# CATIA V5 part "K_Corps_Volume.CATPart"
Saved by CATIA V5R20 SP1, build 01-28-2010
Part number: corps_volume
Publications: "Plan.6", "Raccord roue avant", "Droite.23", "diamètre des barres", "Surepaisseur du tube", "diamètre doight pivot roue avant", "épaisseur raccord", "barres pour roues principales", "raccord des barres principales", "barres soutien", "raccord barres soutien", "petite barre soutien"
Bounding box of the stored display mesh (mm): x -80 to 825, y -400 to 400, z -136.807 to 80
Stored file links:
  G:\Khaled_CFAO_2011\ST2M\ST2M_GR1\cdurantin\cdurantin\Khaled\CAD_ThinkMOTION\K_Corps_Volume.CATPart
  G:\Khaled_CFAO_2011\ST2M\ST2M_GR1\cdurantin\cdurantin\Khaled\CAD_ThinkMOTION\K_Corps.CATPart
  C:\Documents and Settings\cdurantin\Bureau\cdurantin\caddy.CATProduct
  G:\Khaled_CFAO_2011\ST2M\ST2M_GR1\cdurantin\cdurantin\CATIA\Part2.CATPart
  G:\Khaled_CFAO_2011\ST2M\ST2M_GR1\cdurantin\cdurantin\CATIA\pivot roue avant.CATPart
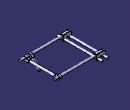
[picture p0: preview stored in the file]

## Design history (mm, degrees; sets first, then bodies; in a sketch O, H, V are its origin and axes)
Parameters
  `diamètre des barres` = 40 mm
  `épaisseur raccord` = 50 mm {= `diamètre des barres` +`Surepaisseur du tube`}
  `Surepaisseur du tube` = 10 mm
  `diamètre doight pivot roue avant` = 5 mm
External parameters (linked from other documents)
  `External.Longueur de barres du corps` = 800 mm
  `External.ecart entre barres de soutien` = 600 mm
  `External.Ecart entre les barres du corps` = 100 mm
  `External.longueur des barres de soutien` = 800 mm
  `External.niveau de la roue avant` = 850 mm
  `External.diamètre tube pivot` = 20 mm
Set1
  Line1 to Line5: linked copy from another document
  Point1: linked copy from another document
  Point2: linked copy from another document
Body1 "barres pour roues principales" (main body)
  Line6: stored without definition
  Point3: stored without definition
  Line7 to Line9: stored without definition
  Sketch1 on zx-plane, origin (0, 0, 0), H (-1, 0, 0), V (0, 0, 1)
    point P1 (-50, 0)
    circle A1 centre (-50, 0) radius 20
    reference projected point E1 (-50, 0) from Line1
    radius A1 = 20 {= `diamètre des barres` /2}
    coincidence: E1 P1
  Pad1: profile Sketch1, direction (0, 1, 0), length 400 {= `External.Longueur de barres du corps` /2}, mirrored extent
  Mirror1: of the body so far, about yz-plane
  Plane1: type Offset, RefPlane zx-plane, Offset 300 {= `External.ecart entre barres de soutien` /2}
  Point4: stored without definition
  Line10: stored without definition
  DatumPoint1
  Line11: stored without definition
  DatumPoint2
  DatumPoint3
  Point5: stored without definition
Body2 "raccord des barres principales"
  Line12: stored without definition
  Line13: stored without definition
  Sketch2 on Plane1, origin (0, 300, 0), H (-1, 0, 0), V (0, 0, 1)
    arc A1 centre (-50, 0) radius 30 from (-80, 0) to (-20, 0) ccw
    arc A2 centre (0, 0) radius 20 from (0, 20) to (-20, 0) ccw
    point P2 (0, 0)
    point P3 (50, 0)
    point P4 (-20, 0)
    reference projected line E1 (100, 0) -> (0, 0) from Line10
    line L1 (-20, 0) -> (-20, 0)
    point P5 (-20, 0)
    point P6 (0, 20)
    line L2 (0, 20) -> (0, 80)
    line L3 (0, 80) -> (-80, 80)
    line L4 (-80, 80) -> (-80, 0)
    point P9 (-80, 0)
    point P10 (-80, 0)
    point P11 (-20, 0)
    reference projected point E2 (0, 0) from Point5
    circle A3 centre (-50, 0) radius 20
    point P12 (-50, 0)
    reference projected point E3 (-50, 0) from axis of face of Pad1 from Sketch1.A1
    radius A1 = 30 {= `Surepaisseur du tube` +`diamètre des barres` /2}
    distance A2 E1 = 20 {= `diamètre des barres` /2}
    length L2 = 60 {= 2*`Surepaisseur du tube` +`diamètre des barres`}
    length L3 = 80 {= `Surepaisseur du tube` +`diamètre des barres` /2+`External.Ecart entre les barres du corps` /2}
    distance P4 E2 = 20 {= `External.Ecart entre les barres du corps` /2-(`diamètre des barres` /2+`Surepaisseur du tube` )}
    radius A3 = 20 {= `diamètre des barres` /2}
    coincidence: P2 V, P3 H, P4 H, P5 A1, P6 V, P9 A1, L1 P11, L4 P10, P5 P11, P9 P10, E3 P12
    horizontal: L1 H, L3 H
    vertical: L2 V
    tangency: L4 A1
    concentricity: A1 A3
  Pad2: profile Sketch2, direction (0, 1, 0), length 25 {= `épaisseur raccord` /2}, mirrored extent
  Mirror2: of the body so far, about yz-plane
  Sketch3 on face of Pad2 from Sketch2.L4, origin (80, 150.6678, 36.0915), H (0, 1, 0), V (0, 0, 1)
    point P1 (149.3322, 13.9085)
    reference projected line E1 (174.3322, 13.9085) -> (174.3322, -36.0915) from edge [face of Pad2 from Sketch2.L4 | end face of Pad2]
    reference projected line E2 (-13.1678, 43.9085) -> (11.8322, 43.9085) from edge [face of Pad2 from Sketch2.L4 | face of Pad2 from Sketch2.L3]
    distance P1 E1 = 25 {= `épaisseur raccord` /2}
    distance P1 E2 = 30 {= `Surepaisseur du tube` +`diamètre des barres` /2}
  Hole1: placed by Sketch3, at (80, 300, 50) direction (-1, 0, 0), diameter 40 {= `diamètre des barres`}, depth 130 {= `Surepaisseur du tube` +`External.Ecart entre les barres du corps` +`diamètre des barres` /2}
  Fillet1: radius 40 {= `diamètre des barres`}, on edge [face of Pad2 | face of Mirror2]
  Fillet2: radius 5, on edge [face of Pad2 | face of Pad2] (x2); edge [face of Pad2 from Sketch2.L4 | face of Pad2]
  Mirror3: of the body so far, about zx-plane
Body3 "barres soutien"
  Plane2 "plan de construction": type Offset, RefPlane yz-plane, Offset 425 {= `External.niveau de la roue avant` /2}
  Sketch4 on Plane2, origin (425, 0, 0), H (0, 1, 0), V (0, 0, 1)
    circle A1 centre (-300, 50) radius 20
    point P1 (-300, 50)
    reference projected point E1 (-300, 50) from Line2
    radius A1 = 20 {= `diamètre des barres` /2}
    coincidence: P1 E1
  Pad3: profile Sketch4, direction (1, 0, 0), length 400 {= `External.longueur des barres de soutien` /2}, mirrored extent
  Plane3: type Offset, RefPlane yz-plane, Offset 400 {= `External.longueur des barres de soutien` /2}
  Sketch5 on Plane3, origin (400, 0, 0), H (0, 1, 0), V (0, 0, 1)
    reference projected point E1 (300, 50) from Line3
    circle A1 centre (300, 50) radius 20
    point P1 (300, 50)
    radius A1 = 20 {= `diamètre des barres` /2}
    coincidence: E1 P1
  Pad4: profile Sketch5, direction (1, 0, 0), length 400 {= `External.longueur des barres de soutien` /2}, mirrored extent
Body4 "raccord barres soutien"
  Plane4: type Offset, RefPlane yz-plane, Offset 720 {= `External.longueur des barres de soutien` -`External.longueur des barres de soutien` /10}
  Sketch6 on Plane4, origin (720, 0, 0), H (0, 1, 0), V (0, 0, 1)
    reference projected point E1 (-300, 50) from Line2
    circle A1 centre (-300, 50) radius 20
    arc A2 centre (-300, 50) radius 25 from (-275, 50) to (-325, 50) ccw
    line L1 (-325, 50) -> (-325, 0)
    line L2 (-325, 0) -> (-225, 0)
    line L3 (-225, 0) -> (-225, 50)
    line L4 (-225, 50) -> (-275, 50)
    radius A1 = 20 {= `diamètre des barres` /2}
    radius A2 = 25 {= `diamètre des barres` /2+`Surepaisseur du tube` /2}
    length L2 = 100 {= `épaisseur raccord` *2}
    length L4 = 50 {= `épaisseur raccord`}
    length L3 = 50 {= `épaisseur raccord`}
    distance L2 H = 0
    concentricity: A1 E1, A2 A1
    tangency: L1 A2
    horizontal: L2 H, L4 H
    vertical: L3 V
  Pad5: profile Sketch6, direction (1, 0, 0), length 25 {= `épaisseur raccord` /2}, mirrored extent
  Fillet3: radius 40 {= `diamètre des barres`}, on edge [face of Pad5 from Sketch6.L2 | face of Pad5 from Sketch6.L1]
  Sketch7 on face of Pad5 from Sketch6.L3, origin (719.5732, -225, 15.4267), H (1, 0, 0), V (0, 0, -1)
    point P1 (0.4268, -9.5733)
    reference projected line E1 (-14.5732, 15.4267) -> (15.4268, 15.4267) from edge [face of Pad5 from Sketch6.L3 | face of Pad5 from Sketch6.L2]
    reference projected line E2 (-24.5732, 15.4267) -> (-24.5732, -14.5733) from edge [start face of Pad5 | face of Pad5 from Sketch6.L3]
    distance P1 E1 = 25 {= `épaisseur raccord` /2}
    distance P1 E2 = 25 {= `épaisseur raccord` /2}
  Hole2: placed by Sketch7, at (720, -225, 25) direction (0, -1, 0), diameter 40 {= `diamètre des barres`}, depth 50 {= `épaisseur raccord`}
  Fillet4: radius 5, on edge [face of Pad5 from Sketch6.A2 | face of Pad5 from Sketch6.L4]; edge [face of Pad5 from Sketch6.L4 | end face of Pad5]; edge [start face of Pad5 | face of Pad5 from Sketch6.L4]; edge [face of Pad5 from Sketch6.L4 | face of Pad5 from Sketch6.L3]; edge [face of Pad5 from Sketch6.L3 | end face of Pad5]; edge [start face of Pad5 | face of Pad5 from Sketch6.L3]; edge [face of Pad5 from Sketch6.L3 | face of Pad5 from Sketch6.L2]; edge [face of Pad5 from Sketch6.L2 | end face of Pad5]; edge [start face of Pad5 | face of Pad5 from Sketch6.L2]
  Mirror4: of the body so far, about zx-plane
Body5 "petite barre soutien"
  Sketch8 on Plane4, origin (720, 0, 0), H (0, 1, 0), V (0, 0, 1)
    line L1 (-275, 25) -> (275, 25)
    line L2 (275, 25) -> (275, 5)
    line L3 (275, 5) -> (-275, 5)
    line L4 (-275, 5) -> (-275, 25)
    reference projected line E1 (150, 50) -> (-150, 50) from Line4
    distance L1 E1 = 25 {= `Surepaisseur du tube` /2+`diamètre des barres` /2}
    length L2 = 20 {= `diamètre des barres` /2}
    distance L2 L4 = 550 {= `External.ecart entre barres de soutien` -`diamètre des barres` -`Surepaisseur du tube`}
    distance V L2 = 275 {= (`External.ecart entre barres de soutien` -`diamètre des barres` -`Surepaisseur du tube` )/2}
    horizontal: L1 H, L3 H
    vertical: L2 V, L4 V
  Shaft1: profile Sketch8, axis Sketch8.L1, angle 360
Body6 "Raccord roue avant"
  Plane5: type Offset, RefPlane yz-plane, Offset 640 {= `External.longueur des barres de soutien` -`External.longueur des barres de soutien` /5}
  Sketch9 on Plane5, origin (640, 0, 0), H (0, 1, 0), V (0, 0, 1)
    circle A1 centre (-300, 50) radius 20
    reference projected point E2 (-300, 50) from axis of face of Pad3 from Sketch4.A1
    arc A2 centre (-300, 50) radius 25 from (-282.3223, 67.6777) to (-317.6777, 32.3223) ccw
    reference projected line E3 (-150, -100) -> (-300, 50) from Line5
    point P5 (-317.6777, 32.3223)
    line L1 (-317.6777, 32.3223) -> (-282.3223, -3.033)
    line L2 (-282.3223, -3.033) -> (-246.967, 32.3223)
    line L3 (-246.967, 32.3223) -> (-282.3223, 67.6777)
    point P8 (-282.3223, 67.6777)
    point P9 (-282.3223, 67.6777)
    point P10 (-317.6777, 32.3223)
    radius A1 = 20 {= `diamètre des barres` /2}
    radius A2 = 25 {= (`diamètre des barres` +`Surepaisseur du tube` )/2}
    length L3 = 50 {= `diamètre des barres` +`Surepaisseur du tube`}
    distance L3 E3 = 25 {= (`diamètre des barres` +`Surepaisseur du tube` )/2}
    length L2 = 50 {= `diamètre des barres` +`Surepaisseur du tube`}
    concentricity: E2 A1, A2 A1
    coincidence: P5 A2, P8 A2, L3 P9, L1 P10
    parallelism: L1 E3
    perpendicularity: L2 E3
  Pad6: profile Sketch9, direction (1, 0, 0), length 25 {= (`diamètre des barres` +`Surepaisseur du tube` )/2}, mirrored extent
  Sketch10 on Plane5, origin (640, 0, 0), H (0, 1, 0), V (0, 0, 1)
    line L1 (-250.5025, 28.7868) -> (-125.2513, -96.4645)
    point P3 (-139.3934, -110.6066)
    line L2 (-139.3934, -110.6066) -> (-264.6447, 14.6447)
    line L3 (-264.6447, 14.6447) -> (-250.5025, 28.7868)
    reference projected point E1 (-300, 50) from Point1
    line L4 (-125.2513, -96.4645) -> (-118.1802, -89.3934)
    line L5 (-118.1802, -89.3934) -> (-111.1091, -96.4645)
    line L6 (-111.1091, -96.4645) -> (-132.3223, -117.6777)
    line L7 (-132.3223, -117.6777) -> (-139.3934, -110.6066)
    point P8 (-139.3934, -110.6066)
    reference projected point E2 (-150, -100) from Point2
    reference projected line E3 (-150, -100) -> (-300, 50) from Line5
    distance L3 E1 = 50 {= `diamètre des barres` +`Surepaisseur du tube`}
    distance L1 L2 = 20 {= `diamètre des barres` /2}
    angle L2 L3 = 90
    length L5 = 10 {= `Surepaisseur du tube`}
    length L6 = 30 {= (`diamètre des barres`/2 +`Surepaisseur du tube` )}
    angle L6 L2 = 90
    angle L1 L4 = 90
    distance L4 E2 = 15 {= `External.diamètre tube pivot`  /2+`Surepaisseur du tube` /2}
    distance L2 E3 = 0
    angle L7 E3 = 180
    parallelism: L5 L1
    coincidence: P8 L4, P3 P8
  Shaft2: profile Sketch10, axis Sketch10.L2, angle 360
  Fillet5: radius 5, on edge [face of Pad6 from Sketch9.A2 | end face of Pad6]; edge [start face of Pad6 | face of Pad6 from Sketch9.L3]; edge [face of Pad6 from Sketch9.L2 | end face of Pad6]; edge [face of Pad6 from Sketch9.L3 | face of Pad6 from Sketch9.L2]; edge [start face of Pad6 | face of Pad6 from Sketch9.L2]; edge [face of Pad6 from Sketch9.L2 | face of Pad6 from Sketch9.L1]; edge [face of Shaft2 from Sketch10.L5 | face of Shaft2 from Sketch10.L6]
  Plane6: type Offset, RefPlane face of Shaft2 from Sketch10.L4, Offset 15 {= (`External.diamètre tube pivot`  +`Surepaisseur du tube` )/2}, reversed
  Sketch11 on Plane6, origin (0, -25, 25), H (-1, 0, 0), V (0, 0.7071, 0.7071)
    arc A1 centre (-640, -176.7767) radius 20 from (-659.3649, -171.7767) to (-659.3649, -181.7767) ccw
    reference projected point E1 (-640, -176.7767) from Line5
    line L1 (-659.3649, -171.7767) -> (-661, -171.7767)
    line L2 (-661, -171.7767) -> (-661, -181.7767)
    line L3 (-661, -181.7767) -> (-659.3649, -181.7767)
    reference projected line E2 through (0, -176.7767) direction (-1, 0) from axis of face of Pad3 from Sketch4.A1
    radius A1 = 20 {= `diamètre des barres` /2}
    length L2 = 10 {= 2*`diamètre doight pivot roue avant`}
    distance L1 E2 = 5 {= `diamètre doight pivot roue avant`}
    distance L2 A1 = 1 {= 1mm}
    concentricity: E1 A1
    horizontal: L1 H, L3 H
    vertical: L2 V
  Sketch12 on Plane5, origin (640, 0, 0), H (0, 1, 0), V (0, 0, 1)
    reference projected point E1 (-150, -100) from Point2
    circle A1 centre (-150, -100) radius 2.5
    radius A1 = 2.5 {= `diamètre doight pivot roue avant` /2}
    concentricity: E1 A1
  SolidCombine1: FirstComponentProfile Sketch11, FirstComponentDirection Sketch11, SecondComponentProfile Sketch12, SecondComponentDirection Sketch12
